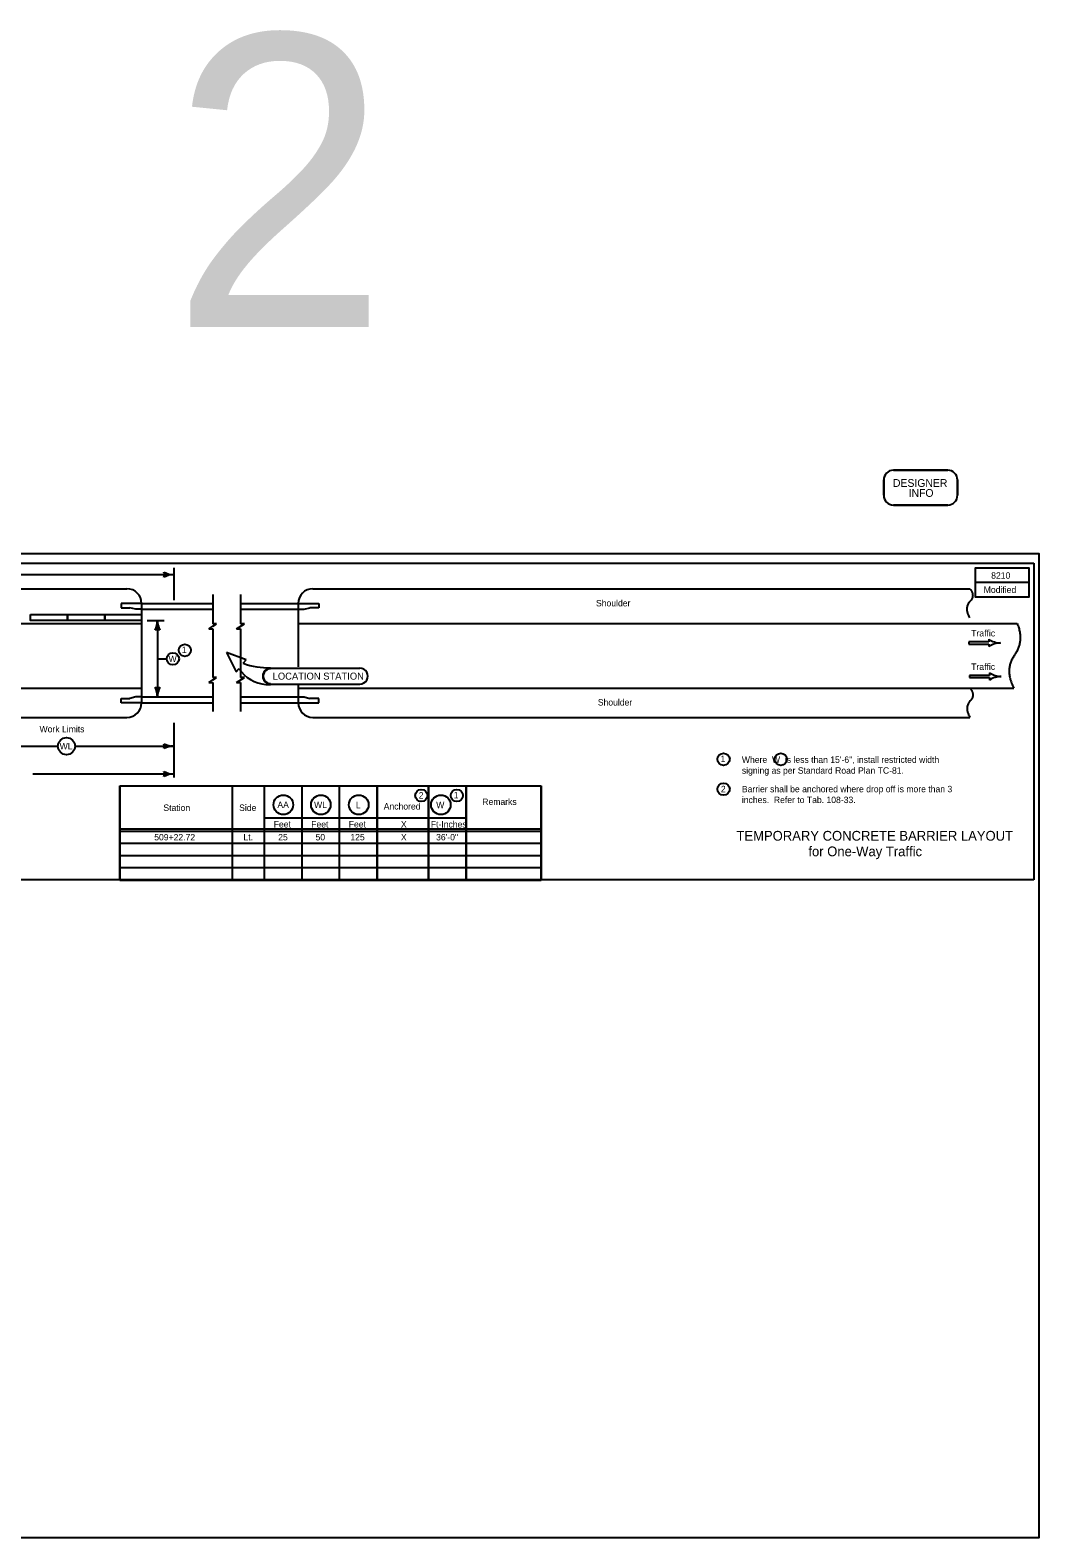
# Model space of a CAD drawing. Extents: x 6410 to 81668, y 3928 to 11667.
# Drawn here: x 14797 to 16868, y 7924 to 11018 of the extents above; entities that cross this region are included whole.
import ezdxf

# ---------------------------------------------------------------- set-up
doc = ezdxf.new("R2010")
doc.units = 0
for name, color, linetype in [('dsnStdDimension', 7, 'Continuous'), ('dsnStdSection', 7, 'Continuous'), ('Level 8', 7, 'Continuous')]:
    doc.layers.add(name, color=color, linetype=linetype)

msp = doc.modelspace()

# ---------------------------------------------------------------- linework, layer by layer
at = {"layer": 'dsnStdDimension'}
for points in [[(16549.1, 10063.5), (16549.1, 10095)], [(16549.1, 10095), (16549.1, 10063.5)], [(16569.1, 10115), (16680.5, 10115)], [(16680.5, 10115), (16569.1, 10115)], [(16700.5, 10095), (16700.5, 10063.5)], [(16700.5, 10063.5), (16700.5, 10095)], [(16680.5, 10043.5), (16569.1, 10043.5)], [(16569.1, 10043.5), (16680.5, 10043.5)]]:
    msp.add_lwpolyline(points, dxfattribs=at)
for centre, start, end in [((16569.1, 10095), 90, 180), ((16569.1, 10095), 90, 180), ((16680.5, 10095), 0, 90), ((16680.5, 10095), 0, 90), ((16569.1, 10063.5), 180, 270), ((16569.1, 10063.5), 180, 270), ((16680.5, 10063.5), 270, 0), ((16680.5, 10063.5), 270, 0)]:
    msp.add_arc(centre, 20, start, end, dxfattribs=at)
at = {"layer": 'dsnStdSection'}
for p, q in [((13752.2, 9924.4), (16857.2, 9924.4)), ((15092, 9914.6), (15092, 9848.4)), ((16857.2, 9924.4), (16857.2, 9274.4)), ((14246.4, 9871.8), (14996, 9871.8)), ((14651.5, 9900.7), (15092, 9900.7)), ((15377.4, 9871.8), (16725.8, 9871.8)), ((15026, 9841.8), (14984, 9841.8)), ((14984, 9841.8), (14984, 9832.8)), ((15026, 9841.8), (15172, 9841.8)), ((15026, 9841.8), (15026, 9637.8)), ((15172, 9859.8), (15172, 9799.8)), ((15229, 9859.8), (15229, 9799.8)), ((15229, 9841.8), (15347.4, 9841.8)), ((15347.4, 9841.8), (15389.4, 9841.8)), ((15347.4, 9841.8), (15347.4, 9711.7)), ((15389.4, 9841.8), (15389.4, 9832.8)), ((14984, 9832.8), (15002, 9832.8)), ((15014, 9829.8), (15002, 9832.8)), ((15026, 9829.8), (15014, 9829.8)), ((15026, 9829.8), (15172, 9829.8)), ((15229, 9829.8), (15347.4, 9829.8)), ((15347.4, 9829.8), (15359.4, 9829.8)), ((15359.4, 9829.8), (15371.4, 9832.8)), ((15389.4, 9832.8), (15371.4, 9832.8)), ((13779.2, 9800.7), (15026, 9800.7)), ((15037.1, 9806.9), (15072, 9806.9)), ((15058.5, 9806.9), (15058.5, 9649.8)), ((15164, 9789.7), (15172, 9794.8)), ((15164, 9789.7), (15172, 9789.7)), ((15172, 9794.8), (15180, 9799.8)), ((15180, 9799.8), (15172, 9799.8)), ((15172, 9789.7), (15172, 9739.8)), ((15221, 9789.7), (15237, 9799.8)), ((15221, 9789.7), (15229, 9789.7)), ((15237, 9799.8), (15229, 9799.8)), ((15229, 9789.7), (15229, 9739.8)), ((15347.4, 9800.7), (16823.1, 9800.7)), ((16764.8, 9762.8), (16723.5, 9762.8)), ((16723.5, 9762.8), (16723.5, 9758.3)), ((16723.5, 9758.3), (16764.8, 9758.3)), ((16764.8, 9768), (16764.8, 9762.8)), ((16764.8, 9758.3), (16764.8, 9753)), ((16788.7, 9760.5), (16788.7, 9760.5)), ((15058.5, 9727.9), (15077.8, 9727.9)), ((15172, 9739.8), (15172, 9689.8)), ((15200.3, 9741.2), (15220.4, 9701.2)), ((15240.5, 9726.2), (15200.3, 9741.2)), ((15229, 9739.8), (15229, 9689.8)), ((15234.6, 9718.8), (15240.5, 9726.2)), ((15164, 9679.7), (15172, 9684.8)), ((15172, 9684.8), (15180, 9689.8)), ((15180, 9689.8), (15172, 9689.8)), ((15220.4, 9701.2), (15226, 9708.2)), ((15221, 9679.7), (15237, 9689.8)), ((15237, 9689.8), (15229, 9689.8)), ((15290.8, 9707.8), (15290.8, 9709.6)), ((15290.8, 9708.7), (15473.9, 9708.7)), ((16766.3, 9694), (16725.1, 9694)), ((16725.1, 9694), (16725.1, 9689.5)), ((16725.1, 9689.5), (16766.3, 9689.5)), ((16766.3, 9699.3), (16766.3, 9694)), ((16766.3, 9689.5), (16766.3, 9684.3)), ((16790.2, 9691.8), (16790.2, 9691.8)), ((13783.9, 9667.8), (15026, 9667.8)), ((15164, 9679.7), (15172, 9679.7)), ((15172, 9679.7), (15172, 9619.8)), ((15221, 9679.7), (15229, 9679.7)), ((15229, 9679.7), (15229, 9619.8)), ((15281.2, 9675.6), (15290.8, 9675.3)), ((15290.8, 9675.3), (15290.8, 9677.1)), ((15290.8, 9676.2), (15473.9, 9676.2)), ((15347.4, 9673.5), (15347.4, 9637.8)), ((15347.4, 9667.8), (16816.1, 9667.8)), ((14984, 9646.8), (15002, 9646.8)), ((14984, 9637.8), (14984, 9646.8)), ((15026, 9637.8), (14984, 9637.8)), ((15014, 9649.8), (15002, 9646.8)), ((15026, 9649.8), (15014, 9649.8)), ((15026, 9649.8), (15172, 9649.8)), ((15026, 9637.8), (15172, 9637.8)), ((15229, 9649.8), (15347.4, 9649.8)), ((15229, 9637.8), (15347.4, 9637.8)), ((15347.4, 9649.8), (15359.4, 9649.8)), ((15347.4, 9637.8), (15389.4, 9637.8)), ((15359.4, 9649.8), (15371.4, 9646.8)), ((15389.4, 9646.8), (15371.4, 9646.8)), ((15389.4, 9637.8), (15389.4, 9646.8)), ((13867.5, 9607.8), (14996, 9607.8)), ((15092, 9596.5), (15092, 9535.3)), ((15092, 9596.5), (15092, 9484.1)), ((15377.4, 9607.8), (16725.8, 9607.8)), ((14721.5, 9548.7), (14854.3, 9548.7)), ((14889.3, 9548.7), (15092, 9548.7)), ((14902, 9548.7), (15092, 9548.7)), ((14802.4, 9491.6), (15092, 9491.6)), ((14803.8, 9491.6), (15092, 9491.6)), ((14981.4, 9467.4), (14981.4, 9274.4)), ((14981.4, 9467.4), (15846, 9467.4)), ((14981.4, 9274.4), (14981.4, 9467.4)), ((14981.4, 9467.4), (15846, 9467.4)), ((15212.4, 9274.4), (15212.4, 9467.4)), ((15278.4, 9274.4), (15278.4, 9467.4)), ((15355.4, 9274.4), (15355.4, 9467.4)), ((15432.4, 9274.4), (15432.4, 9467.4)), ((15432.4, 9274.4), (15432.4, 9467.4)), ((15509.4, 9274.4), (15509.4, 9467.4)), ((15509.4, 9467.4), (15509.4, 9274.4)), ((15615, 9274.4), (15615, 9467.4)), ((15615, 9467.4), (15615, 9274.4)), ((15692, 9274.4), (15692, 9467.4)), ((15692, 9467.4), (15692, 9274.4)), ((15846, 9274.4), (15846, 9467.4)), ((15846, 9467.4), (15846, 9274.4)), ((14981.4, 9379.4), (15846, 9379.4)), ((15278.4, 9401.6), (15692, 9401.6)), ((14981.4, 9374.4), (15846, 9374.4)), ((14981.4, 9349.4), (15846, 9349.4)), ((14981.4, 9324.4), (15846, 9324.4)), ((14981.4, 9299.4), (15846, 9299.4)), ((16857.2, 9274.4), (13752.2, 9274.4)), ((14981.4, 9274), (15846, 9274))]:
    msp.add_line(p, q, dxfattribs=at)
msp.add_lwpolyline([(16847.2, 9914.4), (16847.2, 9854.4), (16737.2, 9854.4), (16737.2, 9914.4), (16847.2, 9914.4), (16847.2, 9884.4), (16737.2, 9884.4)], dxfattribs=at)
for points in [[(14798, 9818.9), (14873, 9818.9), (14873, 9806.9), (14798, 9806.9)], [(14874.5, 9818.9), (14949.5, 9818.9), (14949.5, 9806.9), (14874.5, 9806.9)], [(14951, 9818.9), (15026, 9818.9), (15026, 9806.9), (14951, 9806.9)]]:
    msp.add_lwpolyline(points, close=True, dxfattribs=at)
for centre, radius in [((15114.7, 9745.5), 12.5), ((15090.3, 9727.9), 12.5), ((14871.8, 9548.7), 17.6), ((16220.5, 9521.8), 12.5), ((16337.8, 9521.8), 12.5), ((16220.5, 9460.6), 12.5), ((15316.9, 9428.4), 20.1), ((15393.9, 9428.4), 20.1), ((15471.7, 9428.4), 20.1), ((15600.1, 9447.5), 12.5), ((15640.2, 9428.4), 20.1), ((15672.9, 9447.5), 12.5)]:
    msp.add_circle(centre, radius, dxfattribs=at)
for centre, radius, start, end in [((15056.3, 9900.7), 16.4, 342.2666, 17.7333), ((15092, 9943.2), 42.5, 241.9275, 270), ((14996, 9841.8), 30, 0, 90), ((15092, 9858.2), 42.5, 90, 118.0725), ((15377.4, 9841.8), 30, 90, 180), ((15016, 9806.9), 42.5, 331.9275, 360), ((15058.5, 9771.3), 16.4, 72.2666, 107.7334), ((15101, 9806.9), 42.5, 180, 208.0725), ((16790.7, 9808.8), 48.4, 237.618, 267.648), ((16790.7, 9712.2), 48.4, 92.352, 122.382), ((16792.2, 9740.1), 48.4, 237.618, 267.648), ((16792.2, 9643.5), 48.4, 92.352, 122.382), ((15058.5, 9685.4), 16.4, 252.2666, 287.7333), ((15016, 9649.8), 42.5, 360, 28.0725), ((15101, 9649.8), 42.5, 151.9275, 180), ((14996, 9637.8), 30, 270, 360), ((15377.4, 9637.8), 30, 180, 270), ((15056.3, 9548.7), 16.4, 342.2666, 17.7333), ((15092, 9591.2), 42.5, 241.9275, 270), ((15092, 9506.2), 42.5, 90, 118.0725), ((15056.3, 9491.6), 16.4, 342.2666, 17.7333), ((15092, 9534.1), 42.5, 241.9275, 270), ((15092, 9449.1), 42.5, 90, 118.0725)]:
    msp.add_arc(centre, radius, start, end, dxfattribs=at)
for centre, major_axis, start_param, end_param in [((15287.9, 9865.6), (-156.9, 0), 1.224052, 1.588892), ((15285.8, 9745.9), (-70.8, 0), 0.565405, 1.506314), ((15290.8, 9692.4), (-16.3, 0), 4.712389, 7.853982), ((15290.8, 9692.4), (15.4, 0), 1.570796, 4.712389), ((15473.9, 9692.4), (16.3, 0), 4.712389, 7.853982)]:
    msp.add_ellipse(centre, major_axis=major_axis, ratio=0.995025, start_param=start_param, end_param=end_param, dxfattribs=at)
for points in [[(16725.8, 9871.8), (16737.6, 9857.7), (16714, 9832.7), (16725.3, 9811.8)], [(16823.1, 9800.7), (16837.8, 9764.2), (16796.4, 9705.2), (16816.1, 9667.8)], [(16726.2, 9667.8), (16738, 9653.6), (16714.4, 9628.6), (16725.8, 9607.8)]]:
    msp.add_open_spline(points, degree=2, dxfattribs=at)
at = {"layer": 'Level 8'}
msp.add_lwpolyline([(13732.5, 9944), (16867.5, 9944), (16867.5, 7924), (13732.5, 7924)], close=True, dxfattribs=at)

# ---------------------------------------------------------------- texts
at = {"layer": 'dsnStdDimension'}
for s, p in [('DESIGNER', (16568.1, 10080.8)), ('INFO', (16600.2, 10060.4))]:
    msp.add_text(s, height=16, dxfattribs=at).set_placement(p)
at = {"layer": 'dsnStdSection'}
for s, height, p in [('2', 600, (15085.9, 10409.2)), ('8210', 13.2, (16769.7, 9892.4)), ('Modified', 13.2, (16754.4, 9863.2)), ('Shoulder', 13.2, (15958.6, 9835.6)), ('Traffic', 13.2, (16728.7, 9773.9)), ('1', 13.2, (15108.5, 9739.8)), ('W', 13.2, (15081.3, 9721.3)), ('Traffic', 13.2, (16728.7, 9705.2)), ('LOCATION STATION', 14.4, (15295, 9685.2)), ('Shoulder', 13.2, (15962.3, 9632.1)), ('Work Limits', 13.2, (14816.5, 9577.1)), ('WL', 13.2, (14857.8, 9542.1)), ('1', 13.2, (16214.2, 9516.1)), ('Where  W  is less than 15\'-6", install restricted width', 13.2, (16258, 9514.4)), ('signing as per Standard Road Plan TC-81.', 13.2, (16258, 9492.2)), ('2', 13.2, (15594.8, 9441.2)), ('1', 13.2, (15666.6, 9441.8)), ('Remarks', 13.2, (15725.2, 9428.1)), ('2', 13.2, (16214.9, 9454.1)), ('inches.  Refer to Tab. 108-33.', 13.2, (16258, 9431.9)), ('Barrier shall be anchored where drop off is more than 3 ', 13.2, (16258, 9454.1)), ('Station', 13.2, (15070.7, 9415.8)), ('Side', 13.2, (15226.2, 9415.8)), ('AA', 13.2, (15304.7, 9421.8)), ('WL', 13.2, (15380, 9421.8)), ('L', 13.2, (15465.9, 9421.3)), ('Anchored', 13.2, (15522.9, 9418.7)), ('W', 13.2, (15630.7, 9421.3)), ('Feet', 13.2, (15297.1, 9381.8)), ('Feet', 13.2, (15374.1, 9381.8)), ('Feet', 13.2, (15451.1, 9381.8)), ('X', 13.2, (15558.2, 9381.8)), ('Ft-Inches', 13.2, (15619.6, 9381.8)), ('509+22.72', 13.2, (15051.9, 9355.3)), ('Lt.', 13.2, (15235, 9355.3)), ('25', 13.2, (15306.3, 9355.3)), ('50', 13.2, (15383, 9355.3)), ('125', 13.2, (15454.4, 9355.3)), ('X', 13.2, (15558.2, 9355.3)), ('36\'-0"', 13.2, (15630.4, 9355.3)), ('TEMPORARY CONCRETE BARRIER LAYOUT', 20, (16246.9, 9354.8)), ('for One-Way Traffic', 20, (16394.5, 9322.8))]:
    msp.add_text(s, height=height, dxfattribs=at).set_placement(p)

doc.saveas('drawing.dxf')
